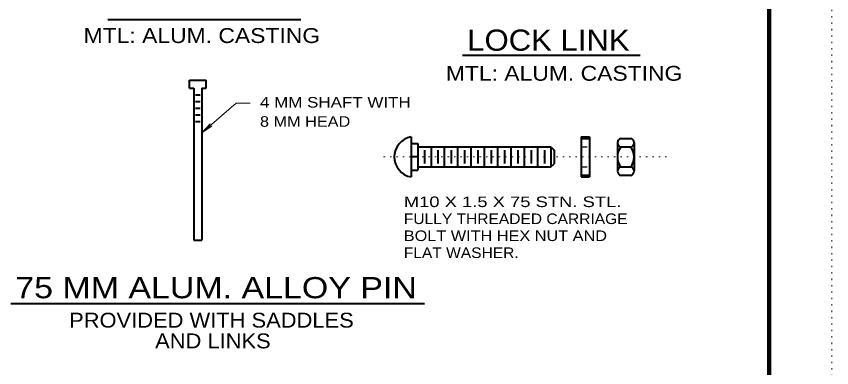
# Model space of a CAD drawing. Extents: x 312583 to 312854, y 144419 to 144597.
# Drawn here: x 312794.9 to 312853.5, y 144524.5 to 144549.8 of the extents above; entities that cross this region are included whole.
import ezdxf
from ezdxf.enums import TextEntityAlignment as Align

# ---------------------------------------------------------------- set-up
doc = ezdxf.new("R2010")
doc.units = 0
doc.header["$LTSCALE"] = 0.3
doc.linetypes.add('DOTTED', pattern=[1.5, 0.3, -1.2])
doc.linetypes.add('SHORT_DASHED', pattern=[2.7, 1.5, -1.2])
for name, color, linetype, lineweight in [('1', 7, 'Continuous', 40), ('2', 7, 'Continuous', 13), ('62', 7, 'DOTTED', 13)]:
    doc.layers.add(name, color=color, linetype=linetype, lineweight=lineweight)

msp = doc.modelspace()

# ---------------------------------------------------------------- linework, layer by layer
at = {"layer": '1', "lineweight": 158}
msp.add_line((312849, 144423.1446), (312849, 144585.0846), dxfattribs=at)
at = {"layer": '1'}
for p, q in [((312807.3333, 144544.6192), (312807.3333, 144545.1942)), ((312807.3333, 144545.1942), (312808.5293, 144545.1942)), ((312808.5293, 144544.6192), (312808.5293, 144545.1942)), ((312807.3333, 144544.6192), (312807.6399, 144544.6192)), ((312807.6399, 144544.6192), (312807.6399, 144533.6942)), ((312807.7626, 144544.1362), (312808.0846, 144544.1362)), ((312808.2149, 144544.6192), (312808.2149, 144533.6942)), ((312808.2149, 144544.6192), (312808.5293, 144544.6192)), ((312807.7626, 144543.6608), (312808.0846, 144543.6608)), ((312807.7626, 144543.1778), (312808.0846, 144543.1778)), ((312807.7626, 144542.7025), (312808.0846, 144542.7025)), ((312807.7626, 144542.2195), (312808.0846, 144542.2195)), ((312823.2569, 144541.1078), (312823.2569, 144538.2328)), ((312823.2569, 144540.6248), (312823.7323, 144540.6248)), ((312823.7323, 144540.6248), (312823.7323, 144538.7082)), ((312835.4776, 144541.1078), (312836.0909, 144541.1078)), ((312835.4776, 144541.1078), (312835.4776, 144538.2328)), ((312835.4776, 144540.9928), (312836.0909, 144540.9928)), ((312836.0909, 144541.1078), (312836.0909, 144538.2328)), ((312838.0996, 144540.7092), (312838.0996, 144538.6622)), ((312838.3373, 144540.9928), (312839.0503, 144540.9928)), ((312839.2956, 144540.7092), (312839.2956, 144538.6622)), ((312823.7323, 144540.3872), (312833.3156, 144540.3872)), ((312824.2153, 144540.1495), (312824.2153, 144539.1912)), ((312824.6906, 144540.3872), (312824.6906, 144538.9458)), ((312825.1736, 144540.1495), (312825.1736, 144539.1912)), ((312825.6489, 144540.3872), (312825.6489, 144538.9458)), ((312826.1319, 144540.1495), (312826.1319, 144539.1912)), ((312826.6073, 144540.3872), (312826.6073, 144538.9458)), ((312827.0903, 144540.1495), (312827.0903, 144539.1912)), ((312827.5656, 144540.3872), (312827.5656, 144538.9458)), ((312828.0486, 144540.1495), (312828.0486, 144539.1912)), ((312828.5239, 144540.3872), (312828.5239, 144538.9458)), ((312829.0069, 144540.1495), (312829.0069, 144539.1912)), ((312829.4823, 144540.3872), (312829.4823, 144538.9458)), ((312829.9653, 144540.1495), (312829.9653, 144539.1912)), ((312830.4406, 144540.3872), (312830.4406, 144538.9458)), ((312830.9236, 144540.1495), (312830.9236, 144539.1912)), ((312831.3989, 144540.3872), (312831.3989, 144538.9458)), ((312831.8819, 144540.1495), (312831.8819, 144539.1912)), ((312832.3573, 144540.3872), (312832.3573, 144538.9458)), ((312832.8403, 144540.1495), (312832.8403, 144539.1912)), ((312833.3156, 144540.3872), (312833.3156, 144538.9458)), ((312833.3156, 144540.3872), (312833.5533, 144540.1495)), ((312833.5533, 144540.1495), (312833.5533, 144539.1835)), ((312838.3373, 144540.3872), (312839.0503, 144540.3872)), ((312823.2569, 144539.6972), (312823.7323, 144539.6972)), ((312823.7323, 144538.9458), (312833.3156, 144538.9458)), ((312833.3156, 144538.9458), (312833.5533, 144539.1835)), ((312838.3373, 144538.9458), (312839.0503, 144538.9458)), ((312823.2569, 144538.7082), (312823.7323, 144538.7082)), ((312835.4776, 144538.3478), (312836.0909, 144538.3478)), ((312835.4776, 144538.2328), (312836.0909, 144538.2328)), ((312838.3373, 144538.3478), (312839.0503, 144538.3478)), ((312807.6399, 144533.6942), (312808.2149, 144533.6942))]:
    msp.add_line(p, q, dxfattribs=at)
at = {"layer": '1', "linetype": 'SHORT_DASHED', "lineweight": 25}
for p, q in [((312835.4776, 144540.3872), (312836.0909, 144540.3872)), ((312835.4776, 144538.9458), (312836.0909, 144538.9458))]:
    msp.add_line(p, q, dxfattribs=at)
at = {"layer": '1', "linetype": 'DOTTED', "lineweight": 13}
msp.add_line((312821.2866, 144539.6665), (312841.9253, 144539.6665), dxfattribs=at)
at = {"layer": '1'}
for centre, radius, start, end in [((312823.5143, 144539.6665), 1.461, 100.29875, 259.70126), ((312838.4064, 144540.6862), 0.3106, 102.8575, 257.14251), ((312838.4064, 144540.6862), 0.3106, 102.8575, 257.14251), ((312838.9811, 144540.6862), 0.3106, 282.85749, 77.1425), ((312838.9811, 144540.6862), 0.3106, 282.85749, 77.1425), ((312839.2861, 144539.6646), 1.1903, 142.85508, 217.14492), ((312839.2861, 144539.6646), 1.1903, 142.85508, 217.14492), ((312838.1015, 144539.6646), 1.1903, 322.85508, 37.14492), ((312838.1015, 144539.6646), 1.1903, 322.85508, 37.14492), ((312838.404, 144538.6449), 0.3082, 102.50121, 257.4988), ((312838.404, 144538.6449), 0.3082, 102.50121, 257.4988), ((312838.9835, 144538.6449), 0.3082, 282.5012, 77.49879), ((312838.9835, 144538.6449), 0.3082, 282.5012, 77.49879)]:
    msp.add_arc(centre, radius, start, end, dxfattribs=at)
at = {"layer": '2', "lineweight": 40}
for p, q in [((312801.4507, 144549.5488), (312815.3407, 144549.5488)), ((312826.963, 144546.9737), (312839.7191, 144546.9737)), ((312794.4706, 144529.1402), (312824.235, 144529.1402))]:
    msp.add_line(p, q, dxfattribs=at)
at = {"layer": '2'}
for p, q in [((312808.2149, 144541.4068), (312808.8053, 144542.0508)), ((312808.2149, 144541.4068), (312808.9433, 144541.8898)), ((312808.8053, 144542.0508), (312808.6673, 144541.7902)), ((312808.9433, 144541.8898), (312808.6673, 144541.7902))]:
    msp.add_line(p, q, dxfattribs=at)
msp.add_lwpolyline([(312808.2149, 144541.4068), (312810.6913, 144543.5228), (312811.6956, 144543.5228)], dxfattribs=at)
at = {"layer": '62'}
msp.add_lwpolyline([(312601.2, 144418.5846), (312853.5, 144418.5846), (312853.5, 144596.7846)], dxfattribs=at)

# ---------------------------------------------------------------- texts
at = {"layer": '2'}
for s, height, width, p in [('MTL: ALUM. CASTING', 1.07, 1.15, (312808.2153, 144547.8541)), ('LOCK LINK', 1.52, 1.1, (312833.1358, 144547.3005)), ('MTL: ALUM. CASTING', 1.07, 1.15, (312834.2588, 144545.1418)), ('75 MM ALUM. ALLOY PIN', 1.52, 1.2, (312809.2377, 144529.5159)), ('PROVIDED WITH SADDLES', 1.07, 1.1, (312808.903, 144527.4051)), ('AND LINKS', 1.07, 1.1, (312809.0097, 144525.9159))]:
    msp.add_text(s, height=height, dxfattribs=dict(at, width=width)).set_placement(p, align=Align.CENTER)
for s, width, p in [('4 MM SHAFT WITH', 1.2, (312812.3933, 144543.2152)), ('8 MM HEAD', 1.15, (312812.3933, 144541.8352)), ('M10 X 1.5 X 75 STN. STL.', 1.3, (312822.7356, 144536.0661)), ('FULLY THREADED CARRIAGE', 1.1, (312822.7356, 144534.8461)), ('BOLT WITH HEX NUT AND', 1.15, (312822.7356, 144533.6261)), ('FLAT WASHER.', 1.1, (312822.7356, 144532.4061))]:
    msp.add_text(s, height=0.76, dxfattribs=dict(at, width=width)).set_placement(p)

doc.saveas('drawing.dxf')
